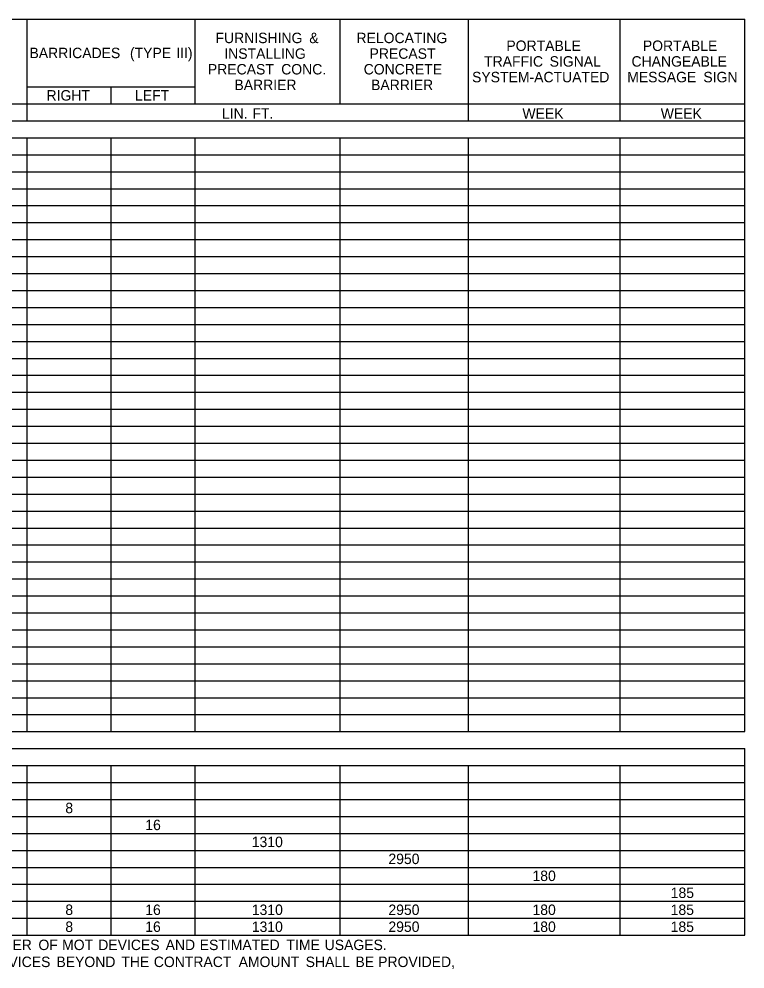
# Model space of a CAD drawing. Extents: x 544420 to 1930787, y -1947044 to 596640.
# Drawn here: x 545209 to 545626, y -1946763 to -1946217 of the extents above; entities that cross this region are included whole.
import ezdxf

# ---------------------------------------------------------------- set-up
doc = ezdxf.new("R2010")
doc.units = 0
doc.layers.add('Default', color=7, linetype='Continuous')

msp = doc.modelspace()

# ---------------------------------------------------------------- linework, layer by layer
at = {"layer": 'Default'}
for p, q in [((544425.9, -1946216.76), (545626.13, -1946216.76)), ((545213.7, -1946275.26), (545213.7, -1946216.76)), ((545310.23, -1946265.51), (545310.23, -1946216.76)), ((545393.59, -1946265.51), (545393.59, -1946216.76)), ((545467.2, -1946275.26), (545467.2, -1946216.76)), ((545554.47, -1946216.76), (545626.13, -1946216.76)), ((545554.47, -1946275.26), (545554.47, -1946216.76)), ((545626.13, -1946626.26), (545626.13, -1946216.76)), ((545213.7, -1946255.76), (545310.23, -1946255.76)), ((545261.97, -1946265.51), (545261.97, -1946255.76)), ((545261.97, -1946265.51), (545261.97, -1946255.76)), ((545002.62, -1946265.51), (545626.13, -1946265.51)), ((545213.7, -1946265.51), (545261.97, -1946265.51)), ((545213.7, -1946275.26), (545213.7, -1946265.51)), ((545261.97, -1946265.51), (545626.13, -1946265.51)), ((545554.47, -1946275.26), (545554.47, -1946265.51)), ((544425.9, -1946275.26), (545626.13, -1946275.26)), ((544944.6, -1946275.26), (545626.13, -1946275.26)), ((544425.9, -1946285.01), (545626.13, -1946285.01)), ((545213.7, -1946558.01), (545213.7, -1946285.01)), ((545213.7, -1946626.26), (545213.7, -1946285.01)), ((545261.97, -1946558.01), (545261.97, -1946285.01)), ((545261.97, -1946626.26), (545261.97, -1946285.01)), ((545310.23, -1946558.01), (545310.23, -1946285.01)), ((545310.23, -1946626.26), (545310.23, -1946285.01)), ((545393.59, -1946558.01), (545393.59, -1946285.01)), ((545393.59, -1946626.26), (545393.59, -1946285.01)), ((545467.2, -1946558.01), (545467.2, -1946285.01)), ((545467.2, -1946626.26), (545467.2, -1946285.01)), ((545554.47, -1946626.26), (545554.47, -1946285.01)), ((544425.9, -1946294.76), (545626.13, -1946294.76)), ((544425.9, -1946304.51), (545626.13, -1946304.51)), ((544425.9, -1946314.26), (545626.13, -1946314.26)), ((544425.9, -1946324.01), (545626.13, -1946324.01)), ((544425.9, -1946333.76), (545626.13, -1946333.76)), ((544425.9, -1946343.51), (545626.13, -1946343.51)), ((544425.9, -1946353.26), (545626.13, -1946353.26)), ((544425.9, -1946363.01), (545626.13, -1946363.01)), ((544425.9, -1946372.76), (545626.13, -1946372.76)), ((544425.9, -1946382.51), (545626.13, -1946382.51)), ((544425.9, -1946392.26), (545626.13, -1946392.26)), ((544425.9, -1946402.01), (545626.13, -1946402.01)), ((544425.9, -1946411.76), (545626.13, -1946411.76)), ((544425.9, -1946421.51), (545626.13, -1946421.51)), ((544425.9, -1946431.26), (545626.13, -1946431.26)), ((544425.9, -1946441.01), (545626.13, -1946441.01)), ((544425.9, -1946450.76), (545626.13, -1946450.76)), ((544425.9, -1946460.51), (545626.13, -1946460.51)), ((544425.9, -1946470.26), (545626.13, -1946470.26)), ((544425.9, -1946480.01), (545626.13, -1946480.01)), ((544425.9, -1946489.76), (545626.13, -1946489.76)), ((544425.9, -1946499.51), (545626.13, -1946499.51)), ((544425.9, -1946509.26), (545626.13, -1946509.26)), ((544425.9, -1946519.01), (545626.13, -1946519.01)), ((544425.9, -1946528.76), (545626.13, -1946528.76)), ((544425.9, -1946538.51), (545626.13, -1946538.51)), ((544425.9, -1946548.26), (545626.13, -1946548.26)), ((544425.9, -1946558.01), (545626.13, -1946558.01)), ((544425.9, -1946567.76), (545626.13, -1946567.76)), ((544425.9, -1946577.51), (545626.13, -1946577.51)), ((544425.9, -1946587.26), (545626.13, -1946587.26)), ((544425.9, -1946597.01), (545626.13, -1946597.01)), ((544425.9, -1946606.76), (545626.13, -1946606.76)), ((544425.9, -1946616.51), (545626.13, -1946616.51)), ((545103.04, -1946616.51), (545626.13, -1946616.51)), ((545213.7, -1946626.26), (545213.7, -1946616.51)), ((545261.97, -1946626.26), (545261.97, -1946616.51)), ((545310.23, -1946626.26), (545310.23, -1946616.51)), ((545393.59, -1946626.26), (545393.59, -1946616.51)), ((545467.2, -1946626.26), (545467.2, -1946616.51)), ((545554.47, -1946626.26), (545554.47, -1946616.51)), ((544425.9, -1946626.26), (545626.13, -1946626.26)), ((544425.9, -1946636.01), (545626.13, -1946636.01)), ((544425.9, -1946636.01), (545626.13, -1946636.01)), ((545626.13, -1946743.26), (545626.13, -1946636.01)), ((544425.9, -1946645.76), (545626.13, -1946645.76)), ((545213.7, -1946743.26), (545213.7, -1946645.76)), ((545213.7, -1946743.26), (545213.7, -1946645.76)), ((545261.97, -1946743.26), (545261.97, -1946645.76)), ((545261.97, -1946743.26), (545261.97, -1946645.76)), ((545310.23, -1946743.26), (545310.23, -1946645.76)), ((545310.23, -1946743.26), (545310.23, -1946645.76)), ((545393.59, -1946743.26), (545393.59, -1946645.76)), ((545393.59, -1946743.26), (545393.59, -1946645.76)), ((545467.2, -1946684.76), (545467.2, -1946645.76)), ((545467.2, -1946743.26), (545467.2, -1946645.76)), ((545554.47, -1946743.26), (545554.47, -1946645.76)), ((544425.9, -1946655.51), (545626.13, -1946655.51)), ((544425.9, -1946665.26), (545626.13, -1946665.26)), ((544425.9, -1946675.01), (545626.13, -1946675.01)), ((544425.9, -1946684.76), (545626.13, -1946684.76)), ((544425.9, -1946694.51), (545626.13, -1946694.51)), ((545002.62, -1946694.51), (545310.23, -1946694.51)), ((545310.23, -1946694.51), (545626.13, -1946694.51)), ((545467.2, -1946743.26), (545467.2, -1946694.51)), ((544425.9, -1946704.26), (545626.13, -1946704.26)), ((544425.9, -1946714.01), (545626.13, -1946714.01)), ((545554.47, -1946723.76), (545554.47, -1946714.01)), ((544425.9, -1946723.76), (545626.13, -1946723.76)), ((545002.62, -1946723.76), (545626.13, -1946723.76)), ((544425.9, -1946733.51), (545626.13, -1946733.51)), ((544425.9, -1946743.26), (545626.13, -1946743.26))]:
    msp.add_line(p, q, dxfattribs=at)

# ---------------------------------------------------------------- texts
for s, p in [('FURNISHING', (545321.96, -1946230.63)), (' &', (545373.62, -1946230.63)), ('RELOCATING', (545402.94, -1946230.63)), (' (TYPE', (545270.58, -1946239.26)), (' III)', (545297.18, -1946239.26)), (' PORTABLE', (545486.82, -1946235.13)), ('PORTABLE', (545567.45, -1946235.13)), ('BARRICADES', (545215.09, -1946239.26)), ('INSTALLING', (545327.01, -1946239.63)), ('PRECAST', (545410.45, -1946239.63)), ('TRAFFIC', (545476.25, -1946244.13)), (' SIGNAL', (545511.67, -1946244.13)), ('CHANGEABLE', (545560.93, -1946244.13)), ('PRECAST', (545317.58, -1946248.63)), (' CONC.', (545357.47, -1946248.63)), ('CONCRETE', (545407.08, -1946248.63)), ('SYSTEM-ACTUATED', (545469.35, -1946253.13)), ('MESSAGE', (545558.46, -1946253.13)), (' SIGN', (545599.98, -1946253.13)), ('BARRIER', (545332.83, -1946257.63)), ('BARRIER', (545411.32, -1946257.63)), ('RIGHT', (545224.88, -1946263.63)), ('LEFT', (545275.71, -1946263.63)), ('LIN.', (545325.66, -1946274.06)), (' FT.', (545340.92, -1946274.06)), ('WEEK', (545498.27, -1946274.06)), ('WEEK', (545577.73, -1946274.06)), ('8', (545235.69, -1946673.13)), ('16', (545281.63, -1946682.88)), ('1310', (545342.79, -1946692.63)), ('2950', (545421.28, -1946702.38)), ('180', (545504.05, -1946712.13)), ('185', (545583.47, -1946721.88)), ('8', (545235.69, -1946731.63)), ('16', (545281.59, -1946731.63)), ('1310', (545342.8, -1946731.63)), ('2950', (545421.28, -1946731.63)), ('180', (545504.05, -1946731.63)), ('185', (545583.43, -1946731.63)), ('8', (545235.69, -1946741.38)), ('16', (545281.59, -1946741.38)), ('1310', (545342.8, -1946741.38)), ('2950', (545421.28, -1946741.38)), ('180', (545504.05, -1946741.38)), ('185', (545583.43, -1946741.38)), (' NUMBER', (545179.46, -1946751.81)), (' OF', (545218.01, -1946751.81)), (' MOT', (545231.6, -1946751.81)), (' DEVICES', (545252.38, -1946751.81)), (' AND', (545291.08, -1946751.81)), (' ESTIMATED', (545310.66, -1946751.81)), (' TIME', (545360.52, -1946751.81)), (' USAGES.', (545382.43, -1946751.81)), (' DEVICES', (545189.66, -1946761.56)), (' BEYOND', (545228.35, -1946761.56)), (' THE', (545265.64, -1946761.56)), (' CONTRACT', (545284.29, -1946761.56)), (' AMOUNT', (545333.03, -1946761.56)), (' SHALL', (545371.52, -1946761.56)), (' BE', (545400.11, -1946761.56)), (' PROVIDED,', (545413.17, -1946761.56))]:
    msp.add_text(s, height=6, dxfattribs=at).set_placement(p)

doc.saveas('drawing.dxf')
